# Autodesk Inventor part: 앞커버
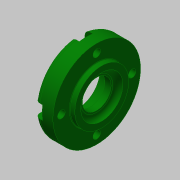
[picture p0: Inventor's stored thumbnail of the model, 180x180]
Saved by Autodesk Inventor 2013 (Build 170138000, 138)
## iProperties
Created: 2015-11
Part Number: 앞커버
Material: 알루미늄 6061
Document SubType Name: Modeling
Designer: mduedu
Density: 1 g/cm^3
Author: mduedu
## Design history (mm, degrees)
sketch "스케치1"
  geometry: L1 (-7, 0)-(7, 0); L2 (-7, 0)-(-7, 26); L3 (-7, 26)-(4, 26); L4 (4, 26)-(4, 16); L5 (4, 16)-(7, 16); L6 (7, 16)-(7, 0); 2 further points
  constraints: 12 end point, 3 perpendicular, 2 parallel, 1 coincident, 1 horizontal, 1 midpoint
  dimensions: "d0" = 14 distance of L1.start L1.end; "d1" = 52 diameter of L3 L1; "d2" = 3 distance of L4.end L5.end; "d3" = 32 diameter of L5 L1
revolve "회전1" sketch "스케치1" stored, may be unused: angle "d4" = 90 deg
hole "구멍1" diameter "d7" = 25; stored, may be unused: countersink angle "d11" = 90 deg, drill point angle "d13" = 0 deg; dims "d5" = 10, "d6" = 10, "d8" = 6, "d9" = 4, "d10" = 2, "d12" = 3
hole "구멍2" diameter "d16" = 25; stored, may be unused: countersink angle "d20" = 90 deg, drill point angle "d22" = 0 deg; dims "d17" = 6, "d18" = 4, "d19" = 2, "d21" = 7.3, "d62" = 10, "d63" = 10
hole "구멍3" diameter "d25" = 17; stored, may be unused: countersink angle "d29" = 90 deg, drill point angle "d31" = 0 deg; dims "d23" = 10, "d24" = 10, "d26" = 6, "d27" = 4, "d28" = 2, "d30" = 4.2
chamfer "모따기1" distance "d32" = 0.7; stored, may be unused: second distance "d33" = 2, angle "d34" = 30 deg
fillet "모깎기1" dims "d35" = 0.3
fillet "모깎기2" dims "d36" = 3
fillet "모깎기3" dims "d37" = 3
fillet "모깎기4" dims "d38" = 0.3
sketch "스케치3" dims "d61" = 42
  geometry: C1 r 26 at (0, 0) reference; 2 further points
  constraints: 2 vertical alignment, 1 coincident, 2 other
hole "구멍4" sketch "스케치3" at (0, -21) diameter "d44" = 4.5; stored, may be unused: countersink angle "d48" = 90 deg, drill point angle "d50" = 0 deg; dims "d45" = 6, "d46" = 8, "d47" = 4.6, "d49" = 8
sketch "스케치4"
  geometry: L1 (-4, 0)-(-4, -4.69); L2 (4, 0)-(4, -4.69); A1 r 4 centre (0, 0) between (3.614, -1.714) and (-3.614, -1.714) reference; A2 r 26 centre (0, 21) between (-4, -4.69) and (4, -4.69) reference; 1 further point
  constraints: 4 end point, 4 point on circle, 2 tangent, 1 parallel, 1 vertical
extrude "돌출1" cut sketch "스케치4" stored distance "d51" = 0; taper "d52" = 0 deg
node "솔리드1"
pattern_circular "원형 패턴1" dims angle "d54" = 360 deg
